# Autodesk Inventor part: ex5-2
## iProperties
Shininess: 64.0
Length Units: 11272
Angle Units: 11279
Time Units: 11290
Mass Units: 11286
Length Display Precision: 3
Angle Display Precision: 2
Compacted: True
Part Number: ex5-2
Document SubType Name: Modeling
Created: 2002-09
Designer: Elise Moss
Density: 0.0
Volumn: 0.0
Area: 0.0
PropertySet Name: Model Information
Control State: 0
Master: False
Checked Out: False
Author: Elise Moss
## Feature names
1. Revolution1
2. Hole1
